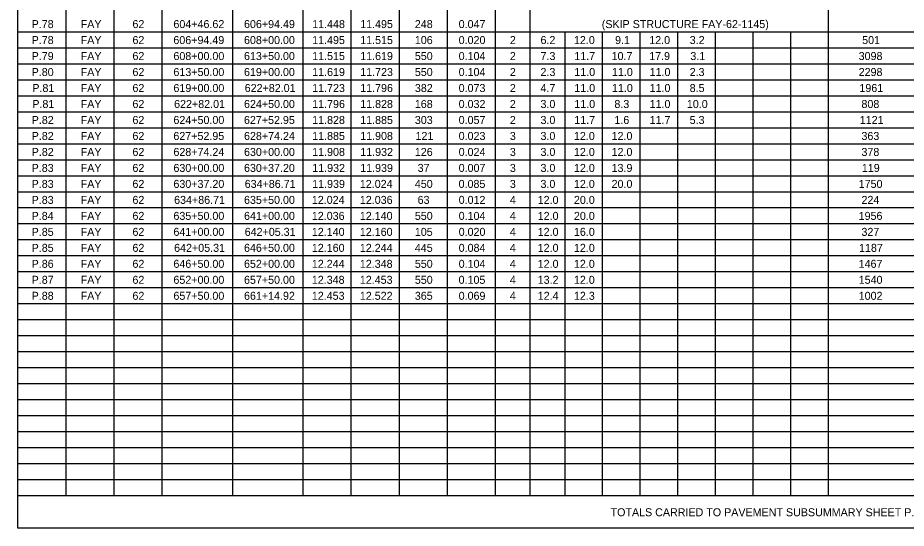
# Model space of a CAD drawing. Extents: x 12522 to 13018, y 1124 to 1902.
# Drawn here: x 12797.22 to 12812.77, y 1756.37 to 1765.31 of the extents above; entities that cross this region are included whole.
import ezdxf

# ---------------------------------------------------------------- set-up
doc = ezdxf.new("R2010")
doc.units = 0
for name, color, linetype in [('SC_Scratch1', 7, 'Continuous'), ('SH_Data', 7, 'Continuous'), ('SH_Text', 7, 'Continuous')]:
    doc.layers.add(name, color=color, linetype=linetype)

msp = doc.modelspace()

# ---------------------------------------------------------------- linework, layer by layer
at = {"layer": 'SC_Scratch1'}
msp.add_lwpolyline([(12797.224, 1777.368), (12827.724, 1777.368), (12827.724, 1756.368), (12797.224, 1756.368)], close=True, dxfattribs=at)
at = {"layer": 'SH_Data'}
for p, q in [((12805.575, 1777.368), (12805.575, 1756.944)), ((12800.979, 1776.824), (12800.979, 1756.944)), ((12802.215, 1776.824), (12802.215, 1756.944)), ((12803.055, 1776.824), (12803.055, 1756.944)), ((12803.895, 1776.824), (12803.895, 1756.944)), ((12804.735, 1776.824), (12804.735, 1756.944)), ((12806.184, 1776.824), (12806.184, 1756.944)), ((12811.405, 1776.824), (12811.405, 1756.944)), ((12798.064, 1773.744), (12798.064, 1756.944)), ((12798.904, 1773.744), (12798.904, 1756.944)), ((12799.744, 1772.064), (12799.744, 1756.944)), ((12797.224, 1765.064), (12827.678, 1765.064)), ((12806.794, 1765.064), (12806.794, 1756.944)), ((12807.452, 1765.064), (12807.452, 1756.944)), ((12808.111, 1765.064), (12808.111, 1756.944)), ((12808.77, 1765.064), (12808.77, 1756.944)), ((12809.429, 1765.064), (12809.429, 1756.944)), ((12810.088, 1765.064), (12810.088, 1756.944)), ((12810.747, 1765.064), (12810.747, 1756.944)), ((12797.224, 1764.784), (12827.678, 1764.784)), ((12797.224, 1764.504), (12827.678, 1764.504)), ((12797.224, 1764.224), (12827.678, 1764.224)), ((12797.224, 1763.944), (12827.678, 1763.944)), ((12797.224, 1763.664), (12827.678, 1763.664)), ((12797.224, 1763.384), (12827.678, 1763.384)), ((12797.224, 1763.104), (12827.678, 1763.104)), ((12797.224, 1762.824), (12827.678, 1762.824)), ((12797.224, 1762.544), (12827.678, 1762.544)), ((12797.224, 1762.264), (12827.678, 1762.264)), ((12797.224, 1761.984), (12827.678, 1761.984)), ((12797.224, 1761.704), (12827.678, 1761.704)), ((12797.224, 1761.424), (12827.678, 1761.424)), ((12797.224, 1761.144), (12827.678, 1761.144)), ((12797.224, 1760.864), (12827.678, 1760.864)), ((12797.224, 1760.584), (12827.678, 1760.584)), ((12797.224, 1760.304), (12827.678, 1760.304)), ((12797.224, 1760.024), (12827.678, 1760.024)), ((12797.224, 1759.744), (12827.678, 1759.744)), ((12797.224, 1759.464), (12827.678, 1759.464)), ((12797.224, 1759.184), (12827.678, 1759.184)), ((12797.224, 1758.904), (12827.678, 1758.904)), ((12797.224, 1758.624), (12827.678, 1758.624)), ((12797.224, 1758.344), (12827.678, 1758.344)), ((12797.224, 1758.064), (12827.678, 1758.064)), ((12797.224, 1757.784), (12827.678, 1757.784)), ((12797.224, 1757.504), (12827.678, 1757.504)), ((12797.224, 1757.224), (12827.678, 1757.224)), ((12797.224, 1756.944), (12827.678, 1756.944))]:
    msp.add_line(p, q, dxfattribs=at)

# ---------------------------------------------------------------- texts
at = {"layer": 'SH_Text'}
for s, p in [('P.78', (12797.467, 1765.13)), ('FAY', (12798.325, 1765.13)), ('62', (12799.231, 1765.13)), ('604+46.62', (12799.948, 1765.13)), ('606+94.49', (12801.183, 1765.13)), ('11.448', (12802.376, 1765.13)), ('11.495', (12803.216, 1765.13)), ('248', (12804.172, 1765.13)), ('0.047', (12804.939, 1765.13)), ('(SKIP STRUCTURE FAY-62-1145)', (12807.443, 1765.13)), ('P.78', (12797.467, 1764.85)), ('FAY', (12798.325, 1764.85)), ('62', (12799.231, 1764.85)), ('606+94.49', (12799.947, 1764.85)), ('608+00.00', (12801.183, 1764.85)), ('11.495', (12802.376, 1764.85)), ('11.515', (12803.216, 1764.85)), ('106', (12804.172, 1764.85)), ('0.020', (12804.939, 1764.85)), ('2', (12805.835, 1764.85)), ('6.2', (12806.371, 1764.85)), ('12.0', (12806.956, 1764.85)), ('9.1', (12807.676, 1764.85)), ('12.0', (12808.274, 1764.85)), ('3.2', (12808.982, 1764.85)), ('501', (12811.999, 1764.85)), ('P.79', (12797.467, 1764.57)), ('FAY', (12798.325, 1764.57)), ('62', (12799.231, 1764.57)), ('608+00.00', (12799.948, 1764.57)), ('613+50.00', (12801.183, 1764.57)), ('11.515', (12802.376, 1764.57)), ('11.619', (12803.216, 1764.57)), ('550', (12804.172, 1764.57)), ('0.104', (12804.939, 1764.57)), ('2', (12805.835, 1764.57)), ('7.3', (12806.371, 1764.57)), ('11.7', (12806.962, 1764.57)), ('10.7', (12807.615, 1764.57)), ('17.9', (12808.273, 1764.57)), ('3.1', (12808.993, 1764.57)), ('3098', (12811.938, 1764.57)), ('P.80', (12797.467, 1764.29)), ('FAY', (12798.325, 1764.29)), ('62', (12799.231, 1764.29)), ('613+50.00', (12799.948, 1764.29)), ('619+00.00', (12801.183, 1764.29)), ('11.619', (12802.376, 1764.29)), ('11.723', (12803.216, 1764.29)), ('550', (12804.172, 1764.29)), ('0.104', (12804.939, 1764.29)), ('2', (12805.835, 1764.29)), ('2.3', (12806.371, 1764.29)), ('11.0', (12806.963, 1764.29)), ('11.0', (12807.621, 1764.29)), ('11.0', (12808.28, 1764.29)), ('2.3', (12808.981, 1764.29)), ('2298', (12811.938, 1764.29)), ('P.81', (12797.479, 1764.01)), ('FAY', (12798.325, 1764.01)), ('62', (12799.231, 1764.01)), ('619+00.00', (12799.948, 1764.01)), ('622+82.01', (12801.195, 1764.01)), ('11.723', (12802.376, 1764.01)), ('11.796', (12803.216, 1764.01)), ('382', (12804.173, 1764.01)), ('0.073', (12804.939, 1764.01)), ('2', (12805.835, 1764.01)), ('4.7', (12806.371, 1764.01)), ('11.0', (12806.963, 1764.01)), ('11.0', (12807.621, 1764.01)), ('11.0', (12808.28, 1764.01)), ('8.5', (12808.981, 1764.01)), ('1961', (12811.951, 1764.01)), ('P.81', (12797.479, 1763.73)), ('FAY', (12798.325, 1763.73)), ('62', (12799.231, 1763.73)), ('622+82.01', (12799.96, 1763.73)), ('624+50.00', (12801.183, 1763.73)), ('11.796', (12802.376, 1763.73)), ('11.828', (12803.216, 1763.73)), ('168', (12804.172, 1763.73)), ('0.032', (12804.939, 1763.73)), ('2', (12805.835, 1763.73)), ('3.0', (12806.371, 1763.73)), ('11.0', (12806.963, 1763.73)), ('8.3', (12807.664, 1763.73)), ('11.0', (12808.28, 1763.73)), ('10.0', (12808.932, 1763.73)), ('808', (12811.987, 1763.73)), ('P.82', (12797.468, 1763.45)), ('FAY', (12798.325, 1763.45)), ('62', (12799.231, 1763.45)), ('624+50.00', (12799.948, 1763.45)), ('627+52.95', (12801.182, 1763.45)), ('11.828', (12802.376, 1763.45)), ('11.885', (12803.216, 1763.45)), ('303', (12804.172, 1763.45)), ('0.057', (12804.939, 1763.45)), ('2', (12805.835, 1763.45)), ('3.0', (12806.371, 1763.45)), ('11.7', (12806.962, 1763.45)), ('1.6', (12807.664, 1763.45)), ('11.7', (12808.28, 1763.45)), ('5.3', (12808.981, 1763.45)), ('1121', (12811.957, 1763.45)), ('P.82', (12797.468, 1763.17)), ('FAY', (12798.325, 1763.17)), ('62', (12799.231, 1763.17)), ('627+52.95', (12799.947, 1763.17)), ('628+74.24', (12801.183, 1763.17)), ('11.885', (12802.376, 1763.17)), ('11.908', (12803.216, 1763.17)), ('121', (12804.184, 1763.17)), ('0.023', (12804.939, 1763.17)), ('3', (12805.835, 1763.17)), ('3.0', (12806.371, 1763.17)), ('12.0', (12806.956, 1763.17)), ('12.0', (12807.615, 1763.17)), ('363', (12811.987, 1763.17)), ('P.82', (12797.468, 1762.89)), ('FAY', (12798.325, 1762.89)), ('62', (12799.231, 1762.89)), ('628+74.24', (12799.948, 1762.89)), ('630+00.00', (12801.183, 1762.89)), ('11.908', (12802.376, 1762.89)), ('11.932', (12803.217, 1762.89)), ('126', (12804.172, 1762.89)), ('0.024', (12804.939, 1762.89)), ('3', (12805.835, 1762.89)), ('3.0', (12806.371, 1762.89)), ('12.0', (12806.956, 1762.89)), ('12.0', (12807.615, 1762.89)), ('378', (12811.987, 1762.89)), ('P.83', (12797.467, 1762.61)), ('FAY', (12798.325, 1762.61)), ('62', (12799.231, 1762.61)), ('630+00.00', (12799.948, 1762.61)), ('630+37.20', (12801.183, 1762.61)), ('11.932', (12802.377, 1762.61)), ('11.939', (12803.216, 1762.61)), ('37', (12804.221, 1762.61)), ('0.007', (12804.939, 1762.61)), ('3', (12805.835, 1762.61)), ('3.0', (12806.371, 1762.61)), ('12.0', (12806.956, 1762.61)), ('13.9', (12807.615, 1762.61)), ('119', (12811.994, 1762.61)), ('P.83', (12797.467, 1762.33)), ('FAY', (12798.325, 1762.33)), ('62', (12799.231, 1762.33)), ('630+37.20', (12799.948, 1762.33)), ('634+86.71', (12801.195, 1762.33)), ('11.939', (12802.376, 1762.33)), ('12.024', (12803.21, 1762.33)), ('450', (12804.172, 1762.33)), ('0.085', (12804.938, 1762.33)), ('3', (12805.835, 1762.33)), ('3.0', (12806.371, 1762.33)), ('12.0', (12806.956, 1762.33)), ('20.0', (12807.615, 1762.33)), ('1750', (12811.939, 1762.33)), ('P.83', (12797.467, 1762.05)), ('FAY', (12798.325, 1762.05)), ('62', (12799.231, 1762.05)), ('634+86.71', (12799.96, 1762.05)), ('635+50.00', (12801.183, 1762.05)), ('12.024', (12802.37, 1762.05)), ('12.036', (12803.21, 1762.05)), ('63', (12804.221, 1762.05)), ('0.012', (12804.939, 1762.05)), ('4', (12805.835, 1762.05)), ('12.0', (12806.322, 1762.05)), ('20.0', (12806.956, 1762.05)), ('224', (12811.988, 1762.05)), ('P.84', (12797.467, 1761.77)), ('FAY', (12798.325, 1761.77)), ('62', (12799.231, 1761.77)), ('635+50.00', (12799.948, 1761.77)), ('641+00.00', (12801.183, 1761.77)), ('12.036', (12802.37, 1761.77)), ('12.140', (12803.21, 1761.77)), ('550', (12804.172, 1761.77)), ('0.104', (12804.939, 1761.77)), ('4', (12805.835, 1761.77)), ('12.0', (12806.322, 1761.77)), ('20.0', (12806.956, 1761.77)), ('1956', (12811.938, 1761.77)), ('P.85', (12797.467, 1761.49)), ('FAY', (12798.325, 1761.49)), ('62', (12799.231, 1761.49)), ('641+00.00', (12799.948, 1761.49)), ('642+05.31', (12801.195, 1761.49)), ('12.140', (12802.37, 1761.49)), ('12.160', (12803.21, 1761.49)), ('105', (12804.172, 1761.49)), ('0.020', (12804.939, 1761.49)), ('4', (12805.835, 1761.49)), ('12.0', (12806.322, 1761.49)), ('16.0', (12806.956, 1761.49)), ('327', (12811.987, 1761.49)), ('P.85', (12797.467, 1761.21)), ('FAY', (12798.325, 1761.21)), ('62', (12799.231, 1761.21)), ('642+05.31', (12799.96, 1761.21)), ('646+50.00', (12801.183, 1761.21)), ('12.160', (12802.37, 1761.21)), ('12.244', (12803.21, 1761.21)), ('445', (12804.172, 1761.21)), ('0.084', (12804.939, 1761.21)), ('4', (12805.835, 1761.21)), ('12.0', (12806.322, 1761.21)), ('12.0', (12806.956, 1761.21)), ('1187', (12811.945, 1761.21)), ('P.86', (12797.467, 1760.93)), ('FAY', (12798.325, 1760.93)), ('62', (12799.231, 1760.93)), ('646+50.00', (12799.948, 1760.93)), ('652+00.00', (12801.183, 1760.93)), ('12.244', (12802.37, 1760.93)), ('12.348', (12803.21, 1760.93)), ('550', (12804.172, 1760.93)), ('0.104', (12804.939, 1760.93)), ('4', (12805.835, 1760.93)), ('12.0', (12806.322, 1760.93)), ('12.0', (12806.956, 1760.93)), ('1467', (12811.938, 1760.93)), ('P.87', (12797.467, 1760.65)), ('FAY', (12798.325, 1760.65)), ('62', (12799.231, 1760.65)), ('652+00.00', (12799.948, 1760.65)), ('657+50.00', (12801.183, 1760.65)), ('12.348', (12802.37, 1760.65)), ('12.453', (12803.21, 1760.65)), ('550', (12804.172, 1760.65)), ('0.105', (12804.938, 1760.65)), ('4', (12805.835, 1760.65)), ('13.2', (12806.322, 1760.65)), ('12.0', (12806.956, 1760.65)), ('1540', (12811.939, 1760.65)), ('P.88', (12797.467, 1760.37)), ('FAY', (12798.325, 1760.37)), ('62', (12799.231, 1760.37)), ('657+50.00', (12799.948, 1760.37)), ('661+14.92', (12801.183, 1760.37)), ('12.453', (12802.37, 1760.37)), ('12.522', (12803.21, 1760.37)), ('365', (12804.172, 1760.37)), ('0.069', (12804.939, 1760.37)), ('4', (12805.835, 1760.37)), ('12.4', (12806.322, 1760.37)), ('12.3', (12806.956, 1760.37)), ('1002', (12811.939, 1760.37)), ('TOTALS CARRIED TO PAVEMENT SUBSUMMARY SHEET P.46', (12807.597, 1756.578))]:
    msp.add_text(s, height=0.14, dxfattribs=at).set_placement(p)

doc.saveas('drawing.dxf')
